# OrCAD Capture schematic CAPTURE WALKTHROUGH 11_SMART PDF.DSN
size A; title: Capture Walkthrough; rev: A; company: EMA Design Automation; note: EMA-12345678; note: 225 Tech Park Dr; note: Rochester, NY
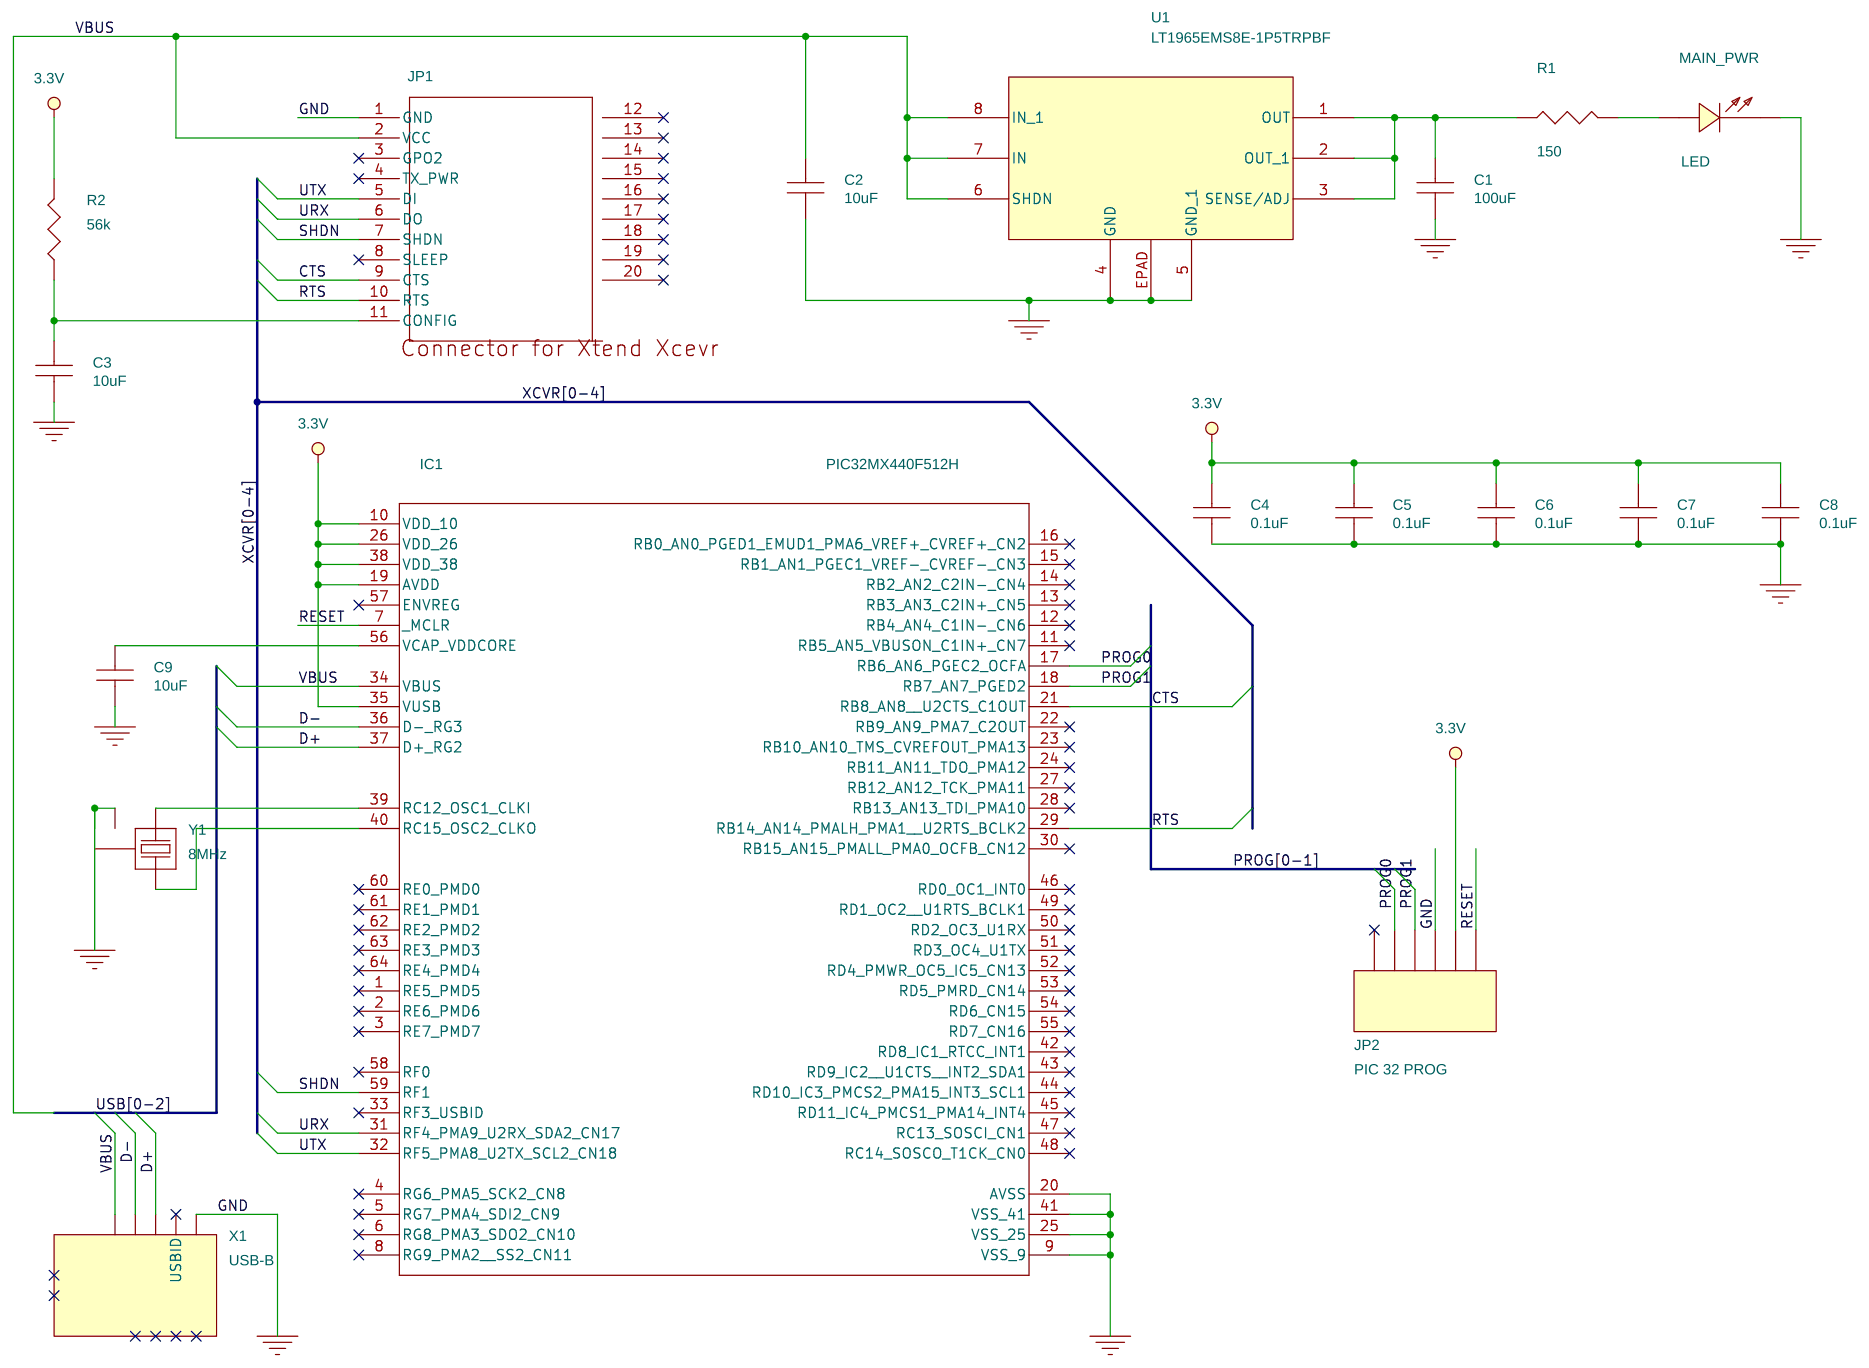
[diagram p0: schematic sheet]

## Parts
C1  100uF  [1210]
C2  10uF  [0402-CAP]
C3  10uF  [0402-CAP]
C4  0.1uF  [0402-CAP]
C5  0.1uF  [0402-CAP]
C6  0.1uF  [0402-CAP]
C7  0.1uF  [0402-CAP]
C8  0.1uF  [0402-CAP]
C9  10uF  [0402-CAP]
IC1  PIC32MX440F512H  [sqfp-s-10x10-64]
JP1  XTEND-DIGI-MODEM  [xtend-digi-modem]
JP2  PIC 32 PROG  [1x06_lock]
MAIN_PWR  LED  [LED_LNJ]
R1  150  [0402-RES]
R2  56k  [0402-RES]
U1  LT1965EMS8E-1P5TRPBF  [MSOP-EP08_3X3_ADI]
X1  USB-B  [USB-MICROB]
Y1  8MHz  [crystal-smd]

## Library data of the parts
C1 = CAP_NP: Manufacturer: Murata; Manufacturer_Part_Number: GRM32EC80J107ME20L; Part Number: 490-6533-1-ND; Vendor: DigiKey
C2 C3 C9 = CAP_NP: Manufacturer: Murata; Manufacturer_Part_Number: GRJ155R60J106ME11D; Part Number: 490-13211-2-ND; Vendor: DigiKey
C4-C8 = CAP_NP: Manufacturer: Samsung; Manufacturer_Part_Number: CL05F104ZO5NNNC; Part Number: 1276-1004-1-ND; Vendor: DigiKey
IC1 = PIC32MX440F512H: Manufacturer: Microchip; Manufacturer_Part_Number: PIC32MX440F512H-MXR; Part Number: PIC32MX440F512H-MXR; Vendor: DigiKey
JP1 = XTEND-DIGI-MODEM: Vendor: DigiKey
JP2 = M06_LOCK: Manufacturer: TE Connectivity; Manufacturer_Part_Number: 640456-6; Part Number: A1923-ND; Vendor: DigiKey
MAIN_PWR = LED: Manufacturer: LITE-ON, INC; Manufacturer_Part_Number: LTST-C191KRKT; Part Number: 160-1447-2-ND; Vendor: DigiKey
R1 = RESISTOR: Manufacturer: Samsung; Manufacturer_Part_Number: RCS1005F151CS; Part Number: RCS1005F151CS-ND; Vendor: DigiKey
R2 = RESISTOR: Manufacturer: Panasonic; Manufacturer_Part_Number: ERA-2AEB563X; Part Number: P56KDCCT-ND; Vendor: DigiKey
U1 = LT1965EMS8E-1P5TRPBF_0: 1.1A, Low Noise, Low Dropout Linear Regulator; Category: PMIC - Voltage Regulators - Linear; Distributor: Digi-Key; Distributor_PN: LT1965EMS8E-1.5#TRPBF-ND; MPN: LT1965EMS8E-1.5#TRPBF; Manufacturer: Analog Devices Inc; Mounting_Type: Surface Mount; Operating_Temperature: -40掳C ~ 125掳C; Package_Case: 8-TSSOP, 8-MSOP (0.118", 3.00mm Width) Exposed Pad; Package_Category: Tape & Reel (TR); Part Number: LT1965EMS8E-1.5#PBF-ND; ROHS: false; Status: Active; Supplier_Device_Package: 8-MSOP-EP; Vendor: DigiKey
X1 = USB-MICROB: Manufacturer: Amphenol; Manufacturer_Part_Number: 10104110-0001LF; Part Number: 609-4052-ND; Vendor: DigiKey
Y1 = CRYSTAL: Manufacturer: Abracon; Manufacturer_Part_Number: ABM3-8MHZ-CL-R500-B1G; Part Number: ABM3-8MHZ-CL-R500-B1G; Vendor: DigiKey

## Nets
3.3V: C4.1 C5.1 C6.1 C7.1 C8.1 IC1.10(VDD) IC1.19(AVDD) IC1.26(VDD) IC1.35(VUSB) IC1.38(VDD) JP2.2 R2.2
GND: C1.2 C2.2 C3.2 C4.2 C5.2 C6.2 C7.2 C8.2 C9.2 IC1.9(VSS) IC1.20(AVSS) IC1.25(VSS) IC1.41(VSS) JP1.1(GND) JP2.3 MAIN_PWR.1(CATHODE) U1.4(GND) U1.5(GND_1) U1.EPAD X1.GND Y1.2(GND) Y1.4(GND)
VBUS: C2.1 IC1.34(VBUS) JP1.2(VCC) U1.6(SHDN) U1.7(IN) U1.8(IN_1) X1.VBUS
CTS: IC1.21(RB8_AN8__U2CTS_C1OUT) JP1.9(CTS)
D+: IC1.37(D+_RG2) X1.D+
D-: IC1.36(D-_RG3) X1.D-
PROG0: IC1.17(RB6_AN6_PGEC2_OCFA) JP2.5
PROG1: IC1.18(RB7_AN7_PGED2) JP2.4
RESET: IC1.7(_MCLR) JP2.1
RTS: IC1.29(RB14_AN14_PMALH_PMA1__U2RTS_BCLK2) JP1.10(RTS)
SHDN: IC1.59(RF1) JP1.7(SHDN)
URX: IC1.31(RF4_PMA9_U2RX_SDA2_CN17) JP1.6(DO)
UTX: IC1.32(RF5_PMA8_U2TX_SCL2_CN18) JP1.5(DI)
N02210: C3.1 JP1.11(CONFIG) R2.1
N02258: IC1.39(RC12_OSC1_CLKI) Y1.1
N02262: IC1.40(RC15_OSC2_CLKO) Y1.3
N02281: C9.1 IC1.56(VCAP_VDDCORE)
N02342: C1.1 R1.1 U1.1(OUT) U1.2(OUT_1) U1.3(SENSE/ADJ)
N02349: MAIN_PWR.2(ANODE) R1.2

Not connected (* = marked no-connect by the designer): IC1 1(RE5_PMD5)* 2(RE6_PMD6)* 3(RE7_PMD7)* 4(RG6_PMA5_SCK2_CN8)* 5(RG7_PMA4_SDI2_CN9)* 6(RG8_PMA3_SDO2_CN10)* 8(RG9_PMA2__SS2_CN11)* 11(RB5_AN5_VBUSON_C1IN+_CN7)* 12(RB4_AN4_C1IN-_CN6)* 13(RB3_AN3_C2IN+_CN5)* 14(RB2_AN2_C2IN-_CN4)* 15(RB1_AN1_PGEC1_VREF-_CVREF-_CN3)* 16(RB0_AN0_PGED1_EMUD1_PMA6_VREF+_CVREF+_CN2)* 22(RB9_AN9_PMA7_C2OUT)* 23(RB10_AN10_TMS_CVREFOUT_PMA13)* 24(RB11_AN11_TDO_PMA12)* 27(RB12_AN12_TCK_PMA11)* 28(RB13_AN13_TDI_PMA10)* 30(RB15_AN15_PMALL_PMA0_OCFB_CN12)* 33(RF3_USBID)* 42(RD8_IC1_RTCC_INT1)* 43(RD9_IC2__U1CTS__INT2_SDA1)* 44(RD10_IC3_PMCS2_PMA15_INT3_SCL1)* 45(RD11_IC4_PMCS1_PMA14_INT4)* 46(RD0_OC1_INT0)* 47(RC13_SOSCI_CN1)* 48(RC14_SOSCO_T1CK_CN0)* 49(RD1_OC2__U1RTS_BCLK1)* 50(RD2_OC3_U1RX)* 51(RD3_OC4_U1TX)* 52(RD4_PMWR_OC5_IC5_CN13)* 53(RD5_PMRD_CN14)* 54(RD6_CN15)* 55(RD7_CN16)* 57(ENVREG)* 58(RF0)* 60(RE0_PMD0)* 61(RE1_PMD1)* 62(RE2_PMD2)* 63(RE3_PMD3)* 64(RE4_PMD4)*; JP1 3(GPO2)* 4(TX_PWR)* 8(SLEEP)* 12* 13* 14* 15* 16* 17* 18* 19* 20*; JP2 6*; X1 ID(USBID)* MT1* MT2* MT3* MT4* P_1* P_2*
